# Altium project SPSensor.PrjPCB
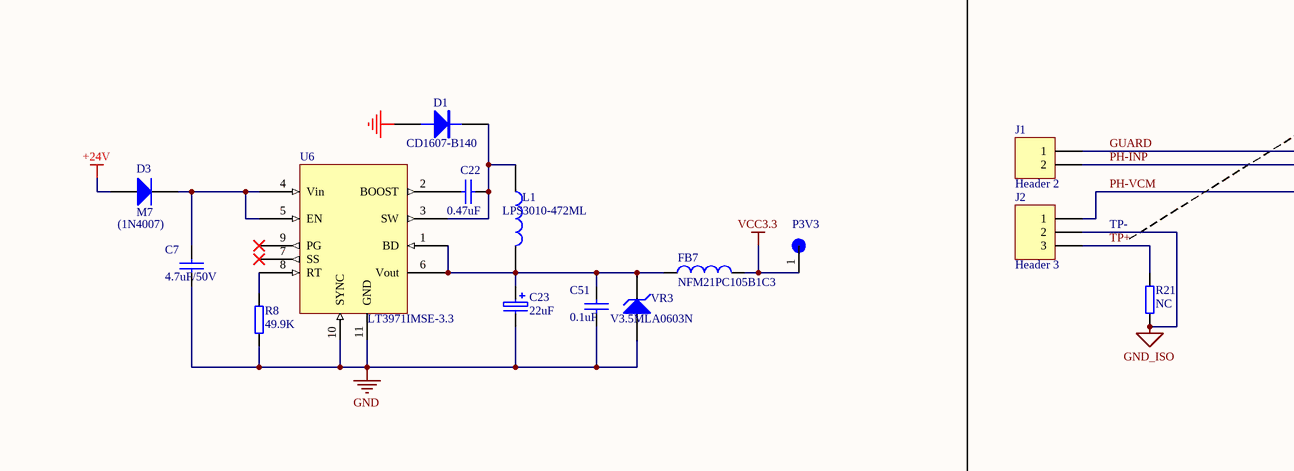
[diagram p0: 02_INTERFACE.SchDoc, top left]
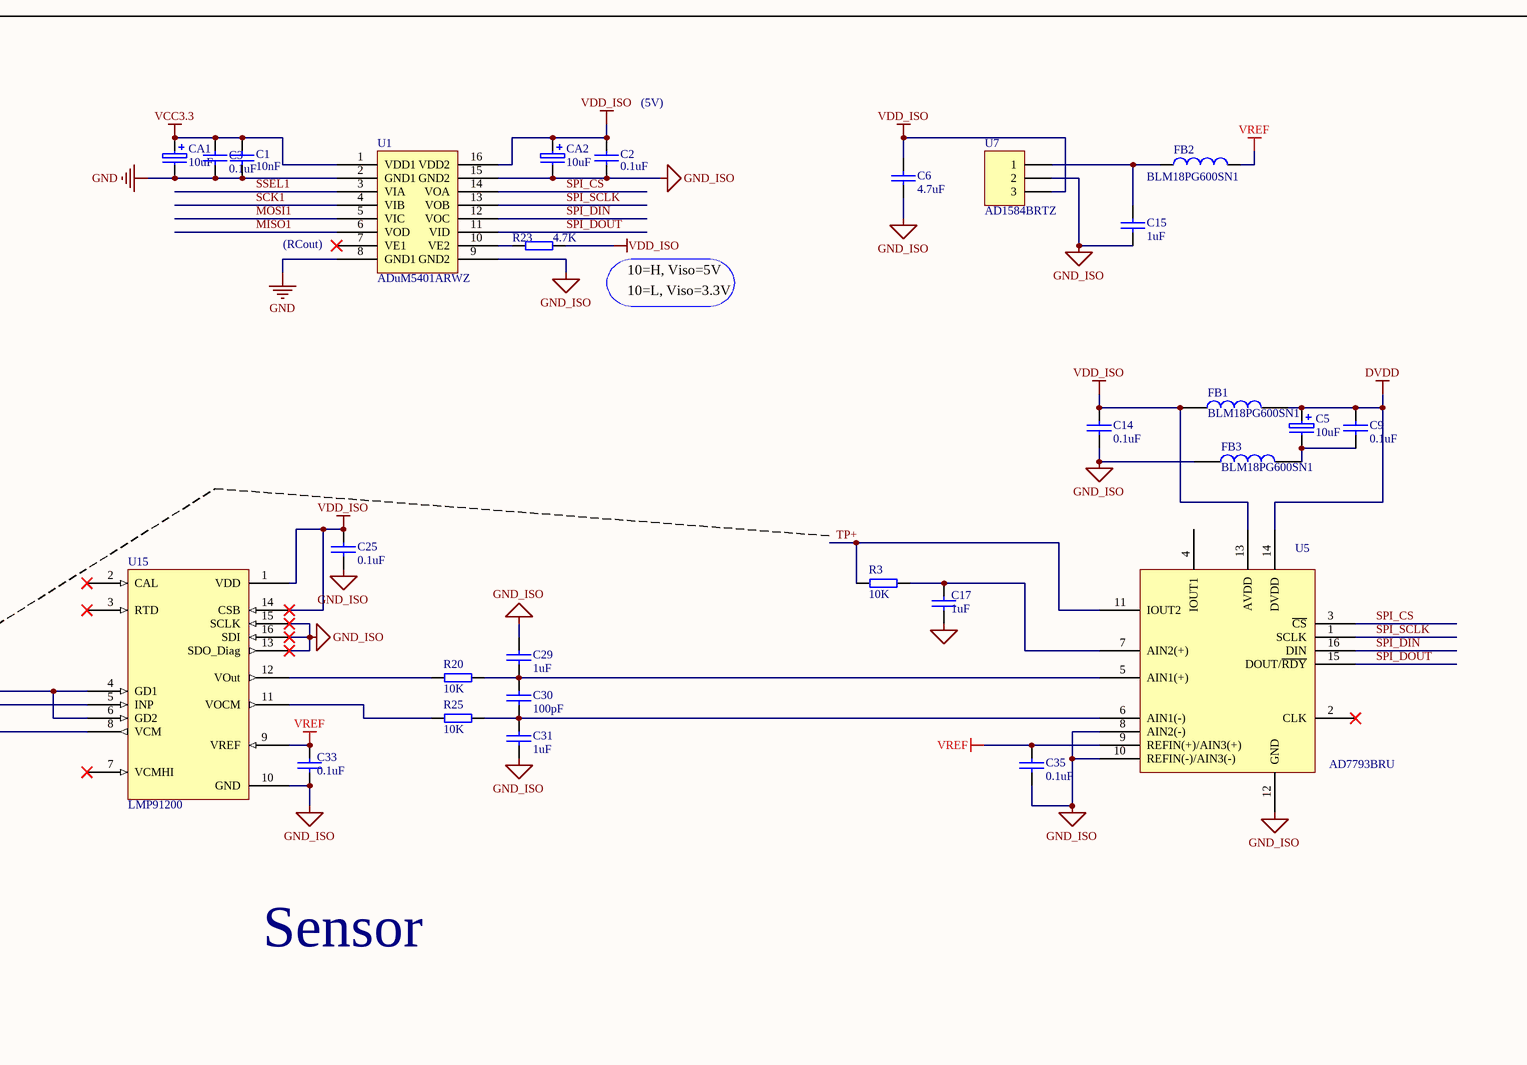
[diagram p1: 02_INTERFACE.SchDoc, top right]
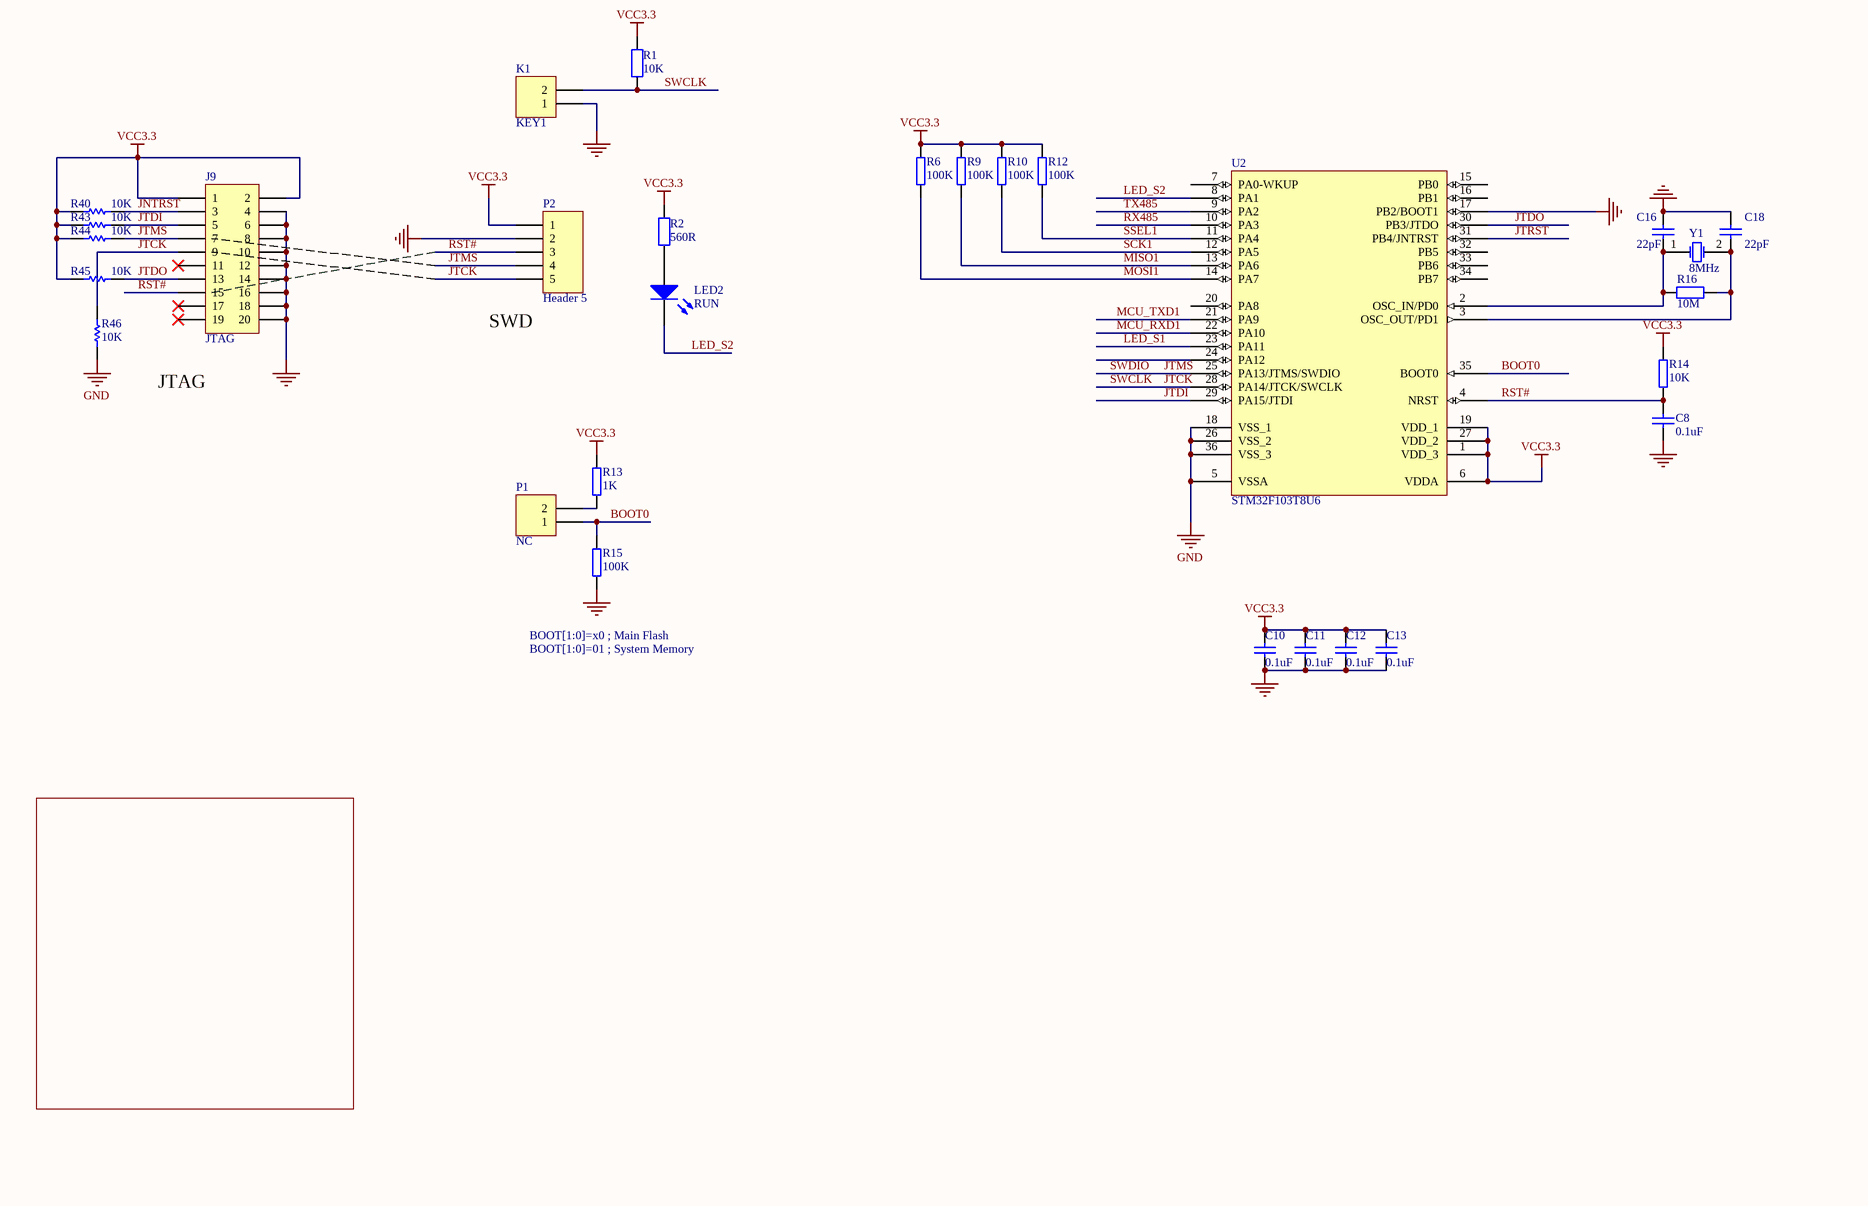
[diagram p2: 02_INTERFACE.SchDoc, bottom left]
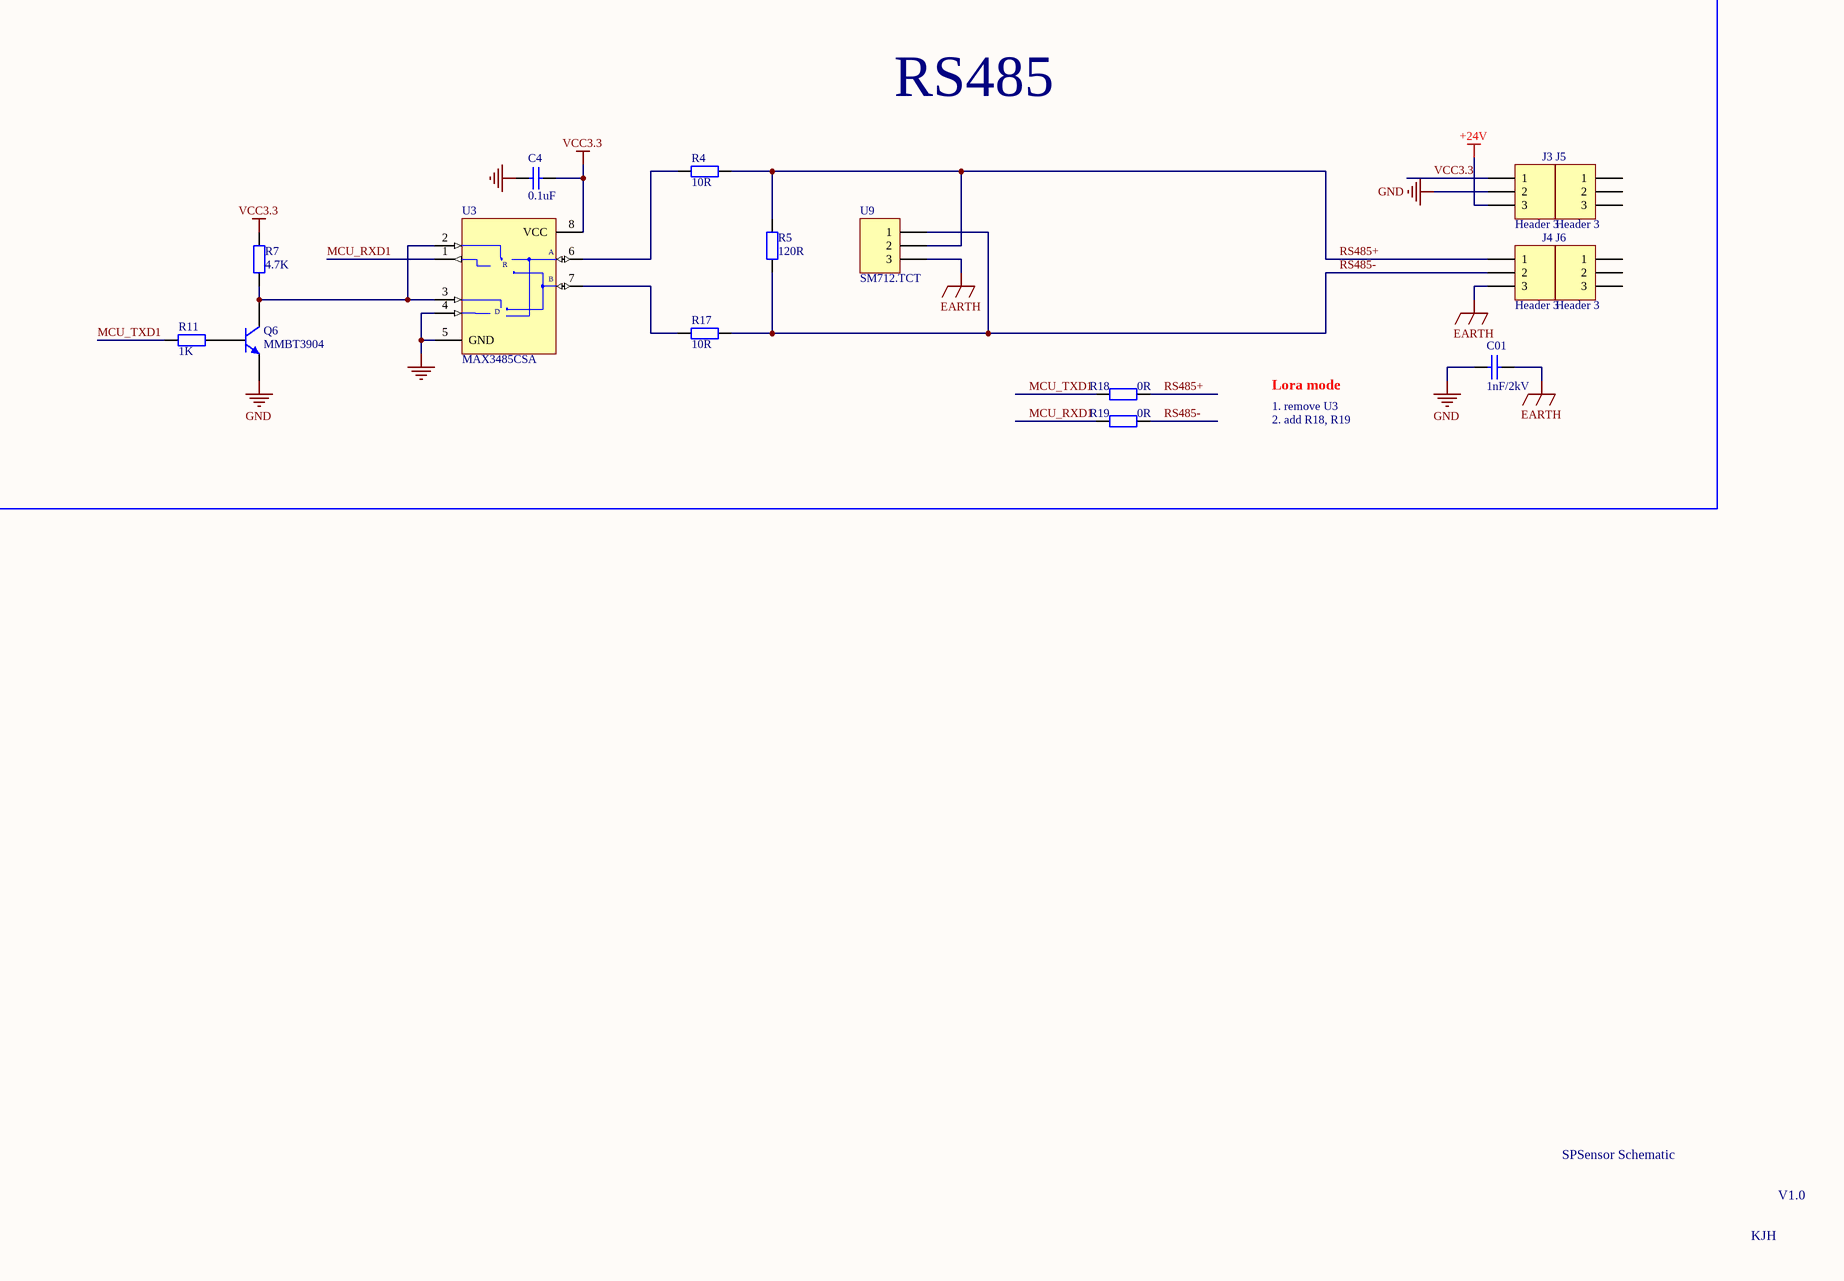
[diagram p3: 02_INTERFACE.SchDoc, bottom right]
1 sheet, 88 parts. Net scope: global (net labels, ports and power ports of the same name join across sheets).
Board file: SPSensor V0.5.PcbDoc

## Sheet 02_INTERFACE.SchDoc
size D; SheetNumber: 0; SheetTotal: 0

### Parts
C1  10nF  [SM0603]
C01  1nF/2kV  [SM1206]
C2  0.1uF  [SM0603]
C3  0.1uF  [SM0603]
C4  0.1uF  [SM0603]
C5  10uF  [SM1206]
C6  4.7uF  [SM0603]
C7  4.7uF/50V  [SM1206]
C8  0.1uF  [SM0603]
C9  0.1uF  [SM0603]
C10  0.1uF  [SM0603]
C11  0.1uF  [SM0603]
C12  0.1uF  [SM0603]
C13  0.1uF  [SM0603]
C14  0.1uF  [SM0603]
C15  1uF  [SM0603]
C16  22pF  [SM0603]
C17  1uF  [SM0603]
C18  22pF  [SM0603]
C22  0.47uF  [SM0603]
C23  22uF  [SM1206]
C25  0.1uF  [SM0603]
C29  1uF  [SM0603]
C30  100pF  [SM0603]
C31  1uF  [SM0603]
C33  0.1uF  [SM0603]
C35  0.1uF  [SM0603]
C51  0.1uF  [SM0603]
CA1  10uF  [SM1206]
CA2  10uF  [SM1206]
D1  CD1607-B140  [1206D]
D3  M7  [1206D]
FB1  BLM18PG600SN1  [SM0603]
FB2  BLM18PG600SN1  [SM0603]
FB3  BLM18PG600SN1  [SM0603]
FB7  NFM21PC105B1C3  [NFM21PC105]
J1  Header 2  [HDR1X2]
J2  Header 3  [HDR1X3]
J3  Header 3  [HDR1X3]
J4  Header 3  [HDR1X3]
J5  Header 3  [HDR1X3]
J6  Header 3  [HDR1X3]
J9  JTAG
K1  KEY1  [SM0603]
L1  LPS3010-472ML  [LPS3010]
LED2  RUN  [SM0805]
P1  NC  [SM0603]
P2  Header 5  [HDR1X5]
P3V3  TestPoint  [test point]  (value not drawn)
Q6  MMBT3904  [SOT23_N]
R1  10K  [SM0603]
R2  560R  [SM0603]
R3  10K  [SM0603]
R4  10R  [SM0603]
R5  120R  [SM0603]
R6  100K  [SM0603]
R7  4.7K  [SM0603]
R8  49.9K  [SM0603]
R9  100K  [SM0603]
R10  100K  [SM0603]
R11  1K  [SM0603]
R12  100K  [SM0603]
R13  1K  [SM0603]
R14  10K  [SM0603]
R15  100K  [SM0603]
R16  10M  [SM0603]
R17  10R  [SM0603]
R18  0R  [SM0603]
R19  0R  [SM0603]
R20  10K  [SM0603]
R21  NC  [SM0603]
R23  4.7K  [SM0603]
R25  10K  [SM0603]
R40  10K
R43  10K
R44  10K
R45  10K
R46  10K
U1  ADuM5401ARWZ  [ADUM1401]
U2  STM32F103T8U6  [VFQN36_V]
U3  MAX3485CSA  [NSO8_N]
U5  AD7793BRU  [AD7793]
U6  LT3971IMSE-3.3  [LT3971]
U7  AD1584BRTZ  [SOT-23]
U9  SM712.TCT  [SOT-23]
U15  LMP91200  [LMP91200]
VR3  V3.5MLA0603N  [SM0603]
Y1  8MHz  [CY5.4X4.6]

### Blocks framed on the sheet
Sensor: C1-C3 C5 C6 C9 C14 C15 C17 C25 C29-C31 C33 C35 CA1 CA2 FB1-FB3 J1 J2 R3 R20 R21 R23 R25 U1 U5 U7 U15
RS485: C01 C4 J3-J6 Q6 R4 R5 R7 R11 R17-R19 U3 U9

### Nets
+24V: D3.1(A) J3.3
DVDD: C5.1 C9.1 FB1.2 U5.14(DVDD)
EARTH: C01.2 J4.3 U9.3
GND: C01.1 C1.2 C3.1 C4.2 C7.2 C8.2 C10.2 C11.2 C12.2 C13.2 C16.2 C18.2 C23.2 C51.2 CA1.2 D1.1(A) J3.2 J9.4 J9.6 J9.8 J9.10 J9.12 J9.14 J9.16 J9.18 J9.20 K1.1 P2.2 Q6.2(E) R8.1 R15.1 R46.1 U1.2(GND1) U1.8(GND1) U2.5(VSSA) U2.17(PB2/BOOT1) U2.18(VSS_1) U2.26(VSS_2) U2.36(VSS_3) U3.4(DI) U3.5(GND) U6.10(SYNC) U6.11(GND) VR3.1(A)
GND_ISO: C2.2 C6.2 C14.2 C15.2 C17.2 C25.2 C29.1 C31.2 C33.2 C35.2 CA2.2 FB3.1 J2.2 R21.1 U1.9(GND2) U1.15(GND2) U5.8(AIN2(-)) U5.10(REFIN(-)/AIN3(-)) U5.12(GND) U7.2 U15.10(GND) U15.13(SDO_Diag) U15.15(SCLK) U15.16(SDI)
VCC3.3: C1.1 C3.2 C4.1 C10.1 C11.1 C12.1 C13.1 CA1.1 FB7.2 J3.1 J9.1 J9.2 P2.1 P3V3.1 R1.1 R2.1 R6.1 R7.2 R9.1 R10.1 R12.1 R13.1 R14.1 R40.1 R43.1 R44.1 R45.1 U1.1(VDD1) U2.1(VDD_3) U2.6(VDDA) U2.19(VDD_1) U2.27(VDD_2) U3.8(VCC)
VDD_ISO: C2.1 C6.1 C14.1 C25.1 CA2.1 FB1.1 R23.2 U1.16(VDD2) U5.13(AVDD) U7.3 U15.1(VDD) U15.14(CSB)
VREF: C33.1 C35.1 FB2.2 U5.9(REFIN(+)/AIN3(+)) U15.9(VREF)
BOOT0: P1.1 R15.2 U2.35(BOOT0)
GUARD: J1.1 U15.4(GD1) U15.6(GD2)
JNTRST: J9.3 R40.2
JTCK: J9.9 K1.2 P2.5 R1.2 R46.2 U2.28(PA14/JTCK/SWCLK)  [also labelled SWCLK]
JTDI: J9.5 R43.2 U2.29(PA15/JTDI)
JTDO: J9.13 R45.2 U2.30(PB3/JTDO)
JTMS: J9.7 P2.4 R44.2 U2.25(PA13/JTMS/SWDIO)  [also labelled SWDIO]
JTRST: U2.31(PB4/JNTRST)
LED_S1: U2.23(PA11)
LED_S2: LED2.2(K) U2.8(PA1)
MCU_RXD1: R19.2 U2.22(PA10) U3.1(RO)
MCU_TXD1: R11.1 R18.2 U2.21(PA9)
MISO1: R9.2 U1.6(VOD) U2.13(PA6)
MOSI1: R6.2 U1.5(VIC) U2.14(PA7)
PH-INP: J1.2 U15.5(INP)
PH-VCM: J2.1 U15.8(VCM)
RS485+: J4.1 R4.1 R5.2 R18.1 U9.2
RS485-: J4.2 R5.1 R17.1 R19.1 U9.1
RST#: C8.1 J9.15 P2.3 R14.2 U2.4(NRST)
RX485: U2.10(PA3)
SCK1: R10.2 U1.4(VIB) U2.12(PA5)
SPI_CS: U1.14(VOA) U5.3(~{CS})
SPI_DIN: U1.12(VOC) U5.16(DIN)
SPI_DOUT: U1.11(VID) U5.15(DOUT/~{RDY})
SPI_SCLK: U1.13(VOB) U5.1(SCLK)
SSEL1: R12.2 U1.3(VIA) U2.11(PA4)
TP+: J2.3 R3.1 R21.2 U5.11(IOUT2)
TX485: U2.9(PA2)
NetC5_2: C5.2 C9.2 FB3.2
NetC7_1: C7.1 D3.2(K) U6.4(Vin) U6.5(EN)
NetC15_1: C15.1 FB2.1 U7.1
NetC16_1: C16.1 R16.1 U2.2(OSC_IN/PD0) Y1.1(OSC1)
NetC17_1: C17.1 R3.2 U5.7(AIN2(+))
NetC18_1: C18.1 R16.2 U2.3(OSC_OUT/PD1) Y1.2(OSC2)
NetC22_1: C22.1 U6.2(BOOST)
NetC22_2: C22.2 D1.2(K) L1.1 U6.3(SW)
NetC23_1: C23.1 C51.1 FB7.1 L1.2 U6.1(BD) U6.6(Vout) VR3.2(K)
NetC29_2: C29.2 C30.1 R20.2 U5.5(AIN1(+))
NetC30_2: C30.2 C31.1 R25.2 U5.6(AIN1(-))
NetLED2_1: LED2.1(A) R2.2
NetP1_2: P1.2 R13.2
NetQ6_1: Q6.1(B) R11.2
NetQ6_3: Q6.3(C) R7.1 U3.2(~{RE}) U3.3(DE)
NetR4_2: R4.2 U3.6(A)
NetR8_2: R8.2 U6.8(RT)
NetR17_2: R17.2 U3.7(B)
NetR20_1: R20.1 U15.12(VOut)
NetR23_1: R23.1 U1.10(VE2)
NetR25_1: R25.1 U15.11(VOCM)

Not connected (* = marked no-connect by the designer): J5 1 2 3; J6 1 2 3; J9 11* 17* 19*; U1 7(VE1)*; U2 7(PA0-WKUP) 15(PB0) 16(PB1) 20(PA8) 24(PA12) 32(PB5) 33(PB6) 34(PB7); U5 2(CLK)* 4(IOUT1); U6 7(SS)* 9(PG)*; U15 2(CAL)* 3(RTD)* 7(VCMHI)*

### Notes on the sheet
- (near C2) (5V)
- (near U1) (RCout)
- 10=H, Viso=5V
- 10=L, Viso=3.3V
- (1N4007)
- TP-
- (near P2) SWD
- JTAG
- 1. remove U3
- 2. add R18, R19
- Lora mode
- BOOT[1:0]=x0 ; Main Flash
- BOOT[1:0]=01 ; System Memory
- SPSensor Schematic
- KJH
- V1.0

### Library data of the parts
C1 C01 C6 C7 C9 C14 C15 C17 C22 C25 C29-C31 C33 C35 C51 = CAP: Capacitor
C2 C3 = C: 电容
C4 C8 = Cap: Capacitor, X7R Ceramic
C5 = CAPE: 极性电容
C10-C13 = Cap: Capacitor
C16 C18 = Cap: Capacitor; Value: 0.1uF
C23 = C: 极性电容
CA1 CA2 = CAPE: Capacitor
D1 = DIODE
D3 = Diode 1N4007: 1 Amp General Purpose Rectifier
FB1 FB3 L1 = INDUCTOR
FB2 FB7 = Inductor: Code_IEC: 1005; Value: 10mH
J1 K1 = Header 2: Header, 2-Pin
J2-J6 = Header 3: Header, 3-Pin
J9 = Header 10X2: Header, 10-Pin, Dual row
LED2 = LED0: Typical INFRARED GaAs LED
P1 = Header 2: Header, 2-Pin, 2.54mm, 排针
P2 = Header 5: Header, 5-Pin
Q6 = MMBT3904: NPN Switching Transistor
R1 R2 R4 R5 R7 R16-R19 = Res2: Resistor; Value: 1K
R3 R6 R9 R10 R12 R20 R21 R25 = RE: 电阻
R8 R13-R15 R23 = R: 电阻
R11 = Res2: Resistor
R40 R43-R46 = Res1: Resistor
U1 = ADUM1401: 1Mbps Data Rate, 100ns Propagation delay
U2 = STM32F103T8U6: STM32 ARM-based 32-bit MCU with 64 Kbytes Flash, 36-pin VFQFPN, Industrial Temperature
U3 = MAX485CSA: Low-Power, Slew-Rate-Limited RS-485/RS-422 Transceiver
U5 = AD7793
U6 = LT3971
U7 = Header 3: 4.096V reference
U9 = Header 3: Asymmerical TVS Diode for RS485
VR3 = D Zener: Zener Diode
Y1 = XTAL: Crystal Oscillator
